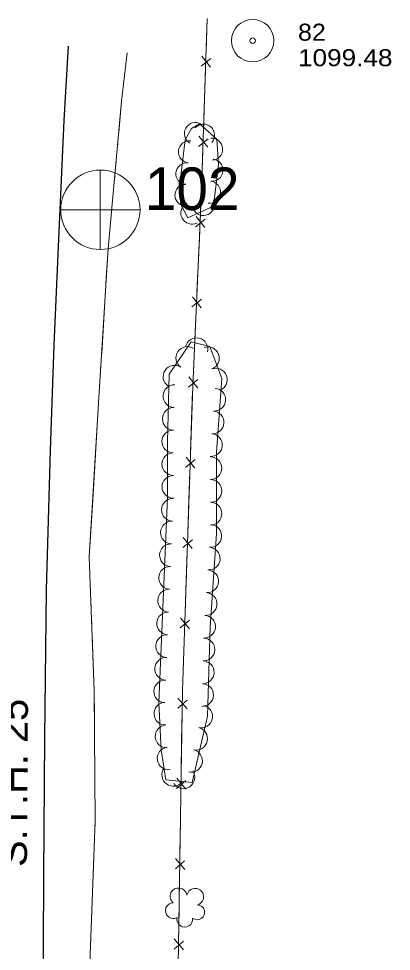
# Model space of a CAD drawing. Extents: x 296583 to 298831, y 44522 to 45957.
# Drawn here: x 297692.9 to 297824.4, y 45510.3 to 45839.4 of the extents above; entities that cross this region are included whole.
import ezdxf

# ---------------------------------------------------------------- set-up
doc = ezdxf.new("R2010")
doc.units = 0
doc.header["$LTSCALE"] = 2.4
for name, color, linetype, lineweight in [('11', 7, 'Continuous', 25), ('15', 7, 'Continuous', 13), ('18', 7, 'Continuous', 13), ('19', 7, 'Continuous', 13), ('4', 7, 'Continuous', 13), ('6', 7, 'Continuous', 13)]:
    doc.layers.add(name, color=color, linetype=linetype, lineweight=lineweight)

msp = doc.modelspace()

# ---------------------------------------------------------------- linework, layer by layer
at = {"layer": '11'}
msp.add_lwpolyline([(297700.604, 45078.854), (297700.618, 45127.759), (297700.405, 45174.635), (297700.7, 45227.338), (297700.641, 45277.618), (297700.756, 45327.982), (297700.817, 45386.673), (297700.954, 45438.105), (297701.512, 45487.567), (297701.749, 45536.979), (297702.068, 45585.788), (297702.731, 45637.819), (297704.078, 45687.047), (297705.432, 45724.307), (297707.239, 45766.902), (297708.944, 45803.473), (297710.461, 45829.675)], dxfattribs=at)
at = {"layer": '15'}
for p, q in [((297759.049, 45827.855), (297759.438, 45839.359)), ((297757.345, 45822.57), (297760.663, 45825.302)), ((297760.63, 45822.286), (297757.467, 45826.174)), ((297758.481, 45811.049), (297758.823, 45821.167)), ((297758.093, 45799.546), (297758.481, 45811.049)), ((297756.388, 45794.26), (297759.706, 45796.993)), ((297759.673, 45793.976), (297756.51, 45797.865)), ((297757.525, 45782.74), (297757.867, 45792.857)), ((297755.319, 45765.972), (297758.667, 45768.667)), ((297758.601, 45765.652), (297755.481, 45769.575)), ((297756.327, 45754.44), (297756.782, 45764.553)), ((297755.81, 45742.941), (297756.327, 45754.44)), ((297754.046, 45737.675), (297757.395, 45740.37)), ((297757.328, 45737.354), (297754.208, 45741.278)), ((297755.054, 45726.142), (297755.509, 45736.256)), ((297754.537, 45714.644), (297755.054, 45726.142)), ((297756.056, 45709.057), (297752.936, 45712.98)), ((297752.774, 45709.378), (297756.122, 45712.073)), ((297753.912, 45697.84), (297754.256, 45707.958)), ((297753.52, 45686.336), (297753.912, 45697.84)), ((297751.815, 45681.052), (297755.134, 45683.783)), ((297755.1, 45680.767), (297751.937, 45684.656)), ((297752.949, 45669.531), (297753.293, 45679.648)), ((297752.558, 45658.027), (297752.949, 45669.531)), ((297750.852, 45652.742), (297754.171, 45655.474)), ((297754.137, 45652.457), (297750.975, 45656.346)), ((297751.986, 45641.221), (297752.33, 45651.339)), ((297751.595, 45629.718), (297751.986, 45641.221)), ((297749.889, 45624.433), (297753.208, 45627.164)), ((297753.175, 45624.148), (297750.012, 45628.037)), ((297751.023, 45612.912), (297751.367, 45623.029)), ((297749.044, 45596.092), (297752.311, 45598.885)), ((297752.334, 45595.869), (297749.099, 45599.698)), ((297750.394, 45584.594), (297750.548, 45594.716)), ((297750.219, 45573.085), (297750.394, 45584.594)), ((297751.903, 45567.546), (297748.668, 45571.375)), ((297748.613, 45567.769), (297751.88, 45570.563)), ((297749.963, 45556.272), (297750.117, 45566.394)), ((297749.788, 45544.763), (297749.963, 45556.272)), ((297748.182, 45539.447), (297751.449, 45542.24)), ((297751.472, 45539.224), (297748.237, 45543.053)), ((297749.532, 45527.949), (297749.686, 45538.071)), ((297749.357, 45516.44), (297749.532, 45527.949)), ((297747.751, 45511.124), (297751.018, 45513.918)), ((297751.041, 45510.901), (297747.806, 45514.73))]:
    msp.add_line(p, q, dxfattribs=at)
for points in [[(297750.954, 45159.736), (297750.312, 45194.971), (297750.417, 45272.978), (297748.709, 45392.083), (297749.076, 45497.953), (297750.665, 45602.374), (297754.315, 45709.699), (297757.299, 45776.061), (297759.438, 45839.359)], [(297757.082, 45771.238), (297757.299, 45776.061), (297757.525, 45782.74)], [(297750.65, 45601.408), (297750.665, 45602.374), (297751.023, 45612.912)]]:
    msp.add_lwpolyline(points, dxfattribs=at)
at = {"layer": '18'}
for points in [[(297749.785, 45780.962), (297749.994, 45774.039), (297752.604, 45769.077), (297761.701, 45773.197), (297763.385, 45787.855), (297762.761, 45796.83), (297756.725, 45802.203), (297753.887, 45800.569), (297751.603, 45796.559)], [(297742.345, 45598.073), (297743.224, 45581.429), (297744.763, 45570.856), (297754.107, 45569.882), (297759.486, 45593.267), (297760.422, 45624.69), (297762.657, 45657.681), (297762.663, 45686.473), (297764.588, 45712.378), (297760.371, 45723.735), (297753.706, 45725.376), (297745.983, 45713.992), (297745.35, 45690.062), (297745.4, 45670.481)]]:
    msp.add_lwpolyline(points, close=True, dxfattribs=at)
for centre, radius, start, end in [((297755.248, 45798.836), 3.898, 60.34286, 240.32754), ((297758.123, 45798.227), 3.898, 318.33349, 138.31817), ((297753.165, 45792.338), 3.898, 83.35922, 263.34389), ((297760.962, 45793.296), 3.898, 273.98483, 93.96951), ((297752.262, 45784.596), 3.898, 83.35922, 263.34389), ((297761.107, 45785.904), 3.898, 263.45391, 83.43859), ((297760.218, 45778.16), 3.898, 263.45391, 83.43859), ((297751.942, 45777.128), 3.898, 91.73685, 271.72153), ((297758.097, 45773.804), 3.898, 204.37327, 24.35795), ((297754.018, 45770.771), 3.898, 117.75192, 297.7366), ((297755.68, 45722.729), 4.01, 346.17589, 166.16057), ((297752.372, 45719.672), 4.01, 55.85437, 235.83904), ((297759.693, 45719.533), 4.01, 290.37827, 110.36295), ((297747.871, 45713.037), 4.01, 55.85437, 235.83904), ((297762.484, 45712.016), 4.01, 290.37827, 110.36295), ((297747.876, 45706.191), 4.01, 88.49242, 268.4771), ((297761.93, 45704.93), 4.01, 265.75783, 85.7425), ((297747.664, 45698.176), 4.01, 88.49242, 268.4771), ((297761.336, 45696.934), 4.01, 265.75783, 85.7425), ((297747.452, 45690.16), 4.01, 88.49242, 268.4771), ((297760.742, 45688.938), 4.01, 265.75783, 85.7425), ((297747.469, 45682.203), 4.01, 90.15397, 270.13864), ((297760.563, 45680.771), 4.01, 269.99572, 89.9804), ((297747.489, 45674.185), 4.01, 90.15397, 270.13864), ((297760.562, 45672.753), 4.01, 269.99572, 89.9804), ((297747.315, 45666.077), 4.01, 87.5917, 267.57638), ((297760.56, 45664.735), 4.01, 269.99572, 89.9804), ((297746.977, 45658.066), 4.01, 87.5917, 267.57638), ((297760.498, 45656.86), 4.01, 266.13204, 86.11672), ((297746.639, 45650.055), 4.01, 87.5917, 267.57638), ((297759.956, 45648.86), 4.01, 266.13204, 86.11672), ((297746.301, 45642.044), 4.01, 87.5917, 267.57638), ((297759.414, 45640.861), 4.01, 266.13204, 86.11672), ((297745.963, 45634.033), 4.01, 87.5917, 267.57638), ((297758.872, 45632.861), 4.01, 266.13204, 86.11672), ((297745.625, 45626.022), 4.01, 87.5917, 267.57638), ((297758.33, 45624.861), 4.01, 266.13204, 86.11672), ((297745.287, 45618.011), 4.01, 87.5917, 267.57638), ((297758.087, 45616.767), 4.01, 268.30149, 88.28617), ((297744.949, 45610), 4.01, 87.5917, 267.57638), ((297757.848, 45608.753), 4.01, 268.30149, 88.28617), ((297744.611, 45601.99), 4.01, 87.5917, 267.57638), ((297757.609, 45600.738), 4.01, 268.30149, 88.28617), ((297744.652, 45594.18), 4.01, 93.03075, 273.01542), ((297757.305, 45593.147), 4.01, 257.05385, 77.03853), ((297745.075, 45586.173), 4.01, 93.03075, 273.01542), ((297755.508, 45585.333), 4.01, 257.05385, 77.03853), ((297745.787, 45578.388), 4.01, 98.28944, 278.27412), ((297753.71, 45577.519), 4.01, 257.05385, 77.03853), ((297747.462, 45572.611), 4.01, 144.05676, 324.04143), ((297750.989, 45571.725), 4.01, 214.05676, 34.04143), ((297749.341, 45529.718), 2.974, 7.98733, 229.22121), ((297755.193, 45529.562), 2.975, 285.63814, 168.61141), ((297747.445, 45524.69), 2.777, 90.95822, 298.73121), ((297755.916, 45524.088), 2.611, 230.34337, 88.27598), ((297751.498, 45521.659), 2.783, 167.63523, 8.64628)]:
    msp.add_arc(centre, radius, start, end, dxfattribs=at)
at = {"layer": '19'}
for p, q in [((297727.664, 45793.322), (297727.842, 45795.268)), ((297727.131, 45787.485), (297727.309, 45789.431)), ((297726.599, 45781.647), (297726.776, 45783.593)), ((297722.167, 45721.244), (297723.923, 45749.521)), ((297721.803, 45715.394), (297721.924, 45717.344)), ((297721.44, 45709.543), (297721.561, 45711.493)), ((297721.081, 45703.693), (297721.2, 45705.643)), ((297719.123, 45671.513), (297720.844, 45699.792)), ((297718.235, 45637.369), (297718.163, 45639.321)), ((297718.451, 45631.511), (297718.379, 45633.464)), ((297718.667, 45625.654), (297718.595, 45627.606)), ((297719.806, 45565.102), (297719.596, 45593.432)), ((297719.849, 45559.24), (297719.835, 45561.194)), ((297719.755, 45553.381), (297719.829, 45555.333)), ((297719.534, 45547.523), (297719.608, 45549.476)), ((297718.318, 45515.307), (297719.386, 45543.618))]:
    msp.add_line(p, q, dxfattribs=at)
for points in [[(297726.055, 45124.806), (297725.401, 45164.864), (297721.448, 45207.244), (297719.634, 45267.49), (297718.877, 45320.671), (297718.675, 45366.263), (297717.075, 45417.239), (297716.686, 45463.269), (297718.083, 45509.09), (297719.87, 45556.428), (297719.531, 45602.258), (297717.786, 45649.534), (297721.321, 45707.634), (297724.469, 45758.303), (297729.206, 45810.224), (297731.165, 45827.332)], [(297728.197, 45799.16), (297729.206, 45810.224), (297731.165, 45827.332)], [(297723.923, 45749.521), (297724.469, 45758.303), (297726.244, 45777.756)], [(297718.019, 45643.226), (297717.786, 45649.534), (297719.123, 45671.513)], [(297719.596, 45593.432), (297719.531, 45602.258), (297718.812, 45621.749)], [(297717.409, 45486.991), (297718.083, 45509.09), (297718.318, 45515.307)]]:
    msp.add_lwpolyline(points, dxfattribs=at)
at = {"layer": '4'}
for p, q in [((297721.657, 45785.951), (297721.592, 45758.097)), ((297707.748, 45771.921), (297735.653, 45771.908))]:
    msp.add_line(p, q, dxfattribs=at)
msp.add_circle((297721.709, 45771.929), 14, dxfattribs=at)
at = {"layer": '6'}
for radius in [7.5, 0.96]:
    msp.add_circle((297775.477, 45831.585), radius, dxfattribs=at)

# ---------------------------------------------------------------- texts
at = {"layer": '11', "width": 1.05}
msp.add_text('S.T.H. 25', height=10, rotation=89.626, dxfattribs=at).set_placement((297695.769, 45540.099))
at = {"layer": '4'}
msp.add_text('102', height=15, dxfattribs=at).set_placement((297737.361, 45771.859))
at = {"layer": '6'}
for s, width, p in [('82', 1.1, (297791.477, 45831.585)), ('1099.48', 1.15, (297791.477, 45822.585))]:
    msp.add_text(s, height=6, dxfattribs=dict(at, width=width)).set_placement(p)

doc.saveas('drawing.dxf')
